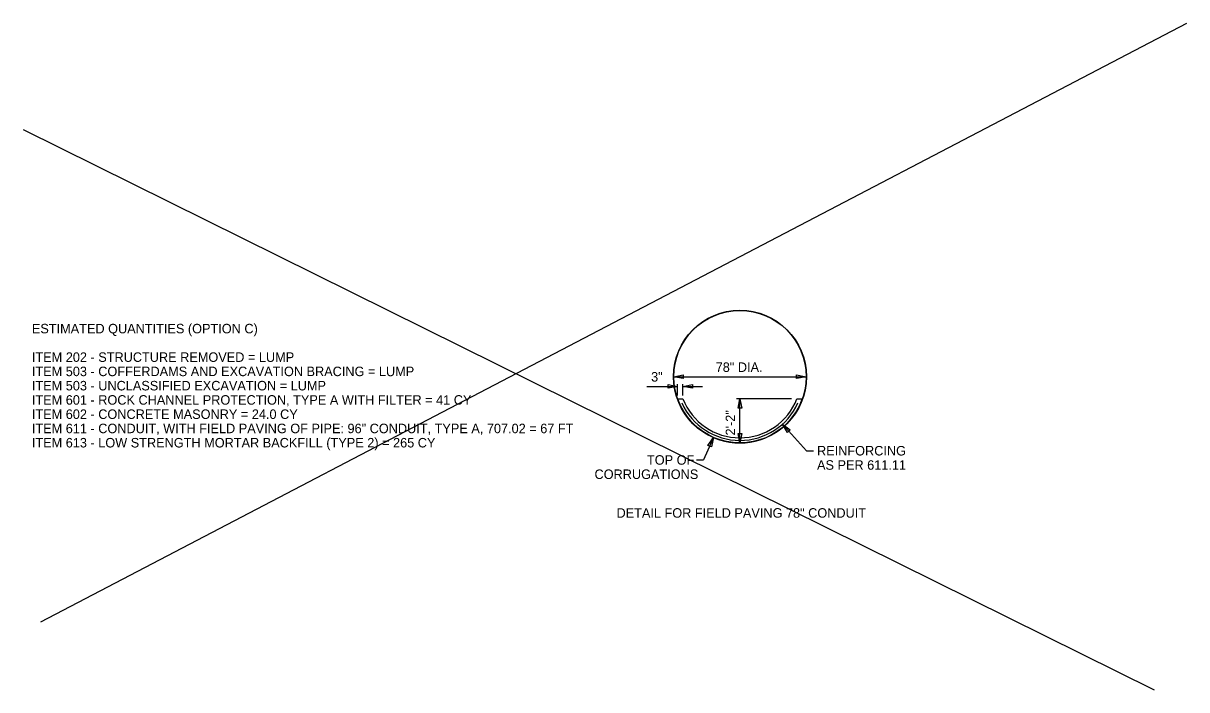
# Model space of a CAD drawing. Extents: x -42 to 540, y 0 to 220.
# Drawn here: x 369 to 540.4, y 79.8 to 177.9 of the extents above; entities that cross this region are included whole.
import ezdxf

# ---------------------------------------------------------------- set-up
doc = ezdxf.new("R2010")
doc.units = 0
for name, color, linetype in [('DR_P_Headwall', 7, 'Continuous'), ('DR_X_Culvert', 7, 'Continuous'), ('SH_Border', 7, 'Continuous'), ('SH_Data', 7, 'Continuous'), ('XS_P_Pavt_Surface', 7, 'Continuous')]:
    doc.layers.add(name, color=color, linetype=linetype)

msp = doc.modelspace()

# ---------------------------------------------------------------- linework, layer by layer
at = {"layer": 'DR_P_Headwall'}
for p, q in [((371.62, 89.77), (540.42, 177.9)), ((369.01, 162.27), (535.64, 79.78))]:
    msp.add_line(p, q, dxfattribs=at)
at = {"layer": 'DR_X_Culvert'}
for points in [[(466.24, 126.15), (466.24, 125.59), (464.84, 125.87)], [(482.94, 125.59), (482.94, 126.15), (484.34, 125.87)], [(464, 124.17), (464, 124.73), (465.4, 124.45)], [(467.6, 124.73), (467.6, 124.17), (466.2, 124.45)], [(474.87, 121.22), (474.31, 121.22), (474.59, 122.62)], [(482, 118.04), (481.58, 117.66), (480.85, 118.89)], [(470.38, 115.54), (469.87, 115.76), (470.68, 116.93)], [(474.31, 117.52), (474.87, 117.52), (474.59, 116.12)]]:
    msp.add_lwpolyline(points, close=True, dxfattribs=at)
at = {"layer": 'SH_Border'}
for radius in [9.79, 9.75]:
    msp.add_circle((474.59, 125.87), radius, dxfattribs=at)
at = {"layer": 'SH_Data'}
for p, q in [((464.84, 125.87), (484.34, 125.87)), ((460.89, 124.45), (465.4, 124.45)), ((465.4, 123.08), (465.4, 124.78)), ((466.2, 123.08), (466.2, 124.78)), ((466.2, 124.45), (469.08, 124.45)), ((465.4, 122.62), (466.2, 122.62)), ((465.4, 122.62), (466.2, 122.62)), ((482.2, 122.62), (474.09, 122.62)), ((474.59, 116.12), (474.59, 122.62)), ((482.98, 122.62), (483.78, 122.62)), ((482.98, 122.62), (483.78, 122.62)), ((480.85, 118.89), (484.38, 114.97)), ((470.68, 116.93), (469.23, 113.61)), ((484.38, 114.97), (485.42, 114.97)), ((468.18, 113.61), (469.23, 113.61))]:
    msp.add_line(p, q, dxfattribs=at)
for radius, start, end in [(9.75, 199.4712, 340.5288), (9, 201.1684, 338.8316), (9, 201.1684, 338.8316)]:
    msp.add_arc((474.59, 125.87), radius, start, end, dxfattribs=at)
at = {"layer": 'XS_P_Pavt_Surface'}
msp.add_arc((474.59, 125.87), 9.38, 204.2242, 335.7758, dxfattribs=at)

# ---------------------------------------------------------------- texts
at = {"layer": 'SH_Data'}
for s, p in [('ESTIMATED QUANTITIES (OPTION C)', (370.28, 132.25)), ('ITEM 202 - STRUCTURE REMOVED = LUMP', (370.28, 128.05)), ('ITEM 503 - COFFERDAMS AND EXCAVATION BRACING = LUMP', (370.28, 125.95)), ('78" DIA.', (471.02, 126.57)), ('ITEM 503 - UNCLASSIFIED EXCAVATION = LUMP', (370.28, 123.85)), ('3"', (461.51, 125.15)), ('ITEM 601 - ROCK CHANNEL PROTECTION, TYPE A WITH FILTER = 41 CY', (370.28, 121.75)), ('ITEM 602 - CONCRETE MASONRY = 24.0 CY', (370.28, 119.65)), ('ITEM 611 - CONDUIT, WITH FIELD PAVING OF PIPE: 96" CONDUIT, TYPE A, 707.02 = 67 FT', (370.28, 117.55)), ('ITEM 613 - LOW STRENGTH MORTAR BACKFILL (TYPE 2) = 265 CY', (370.28, 115.45)), ('REINFORCING', (485.95, 114.27)), ('TOP OF', (460.9, 112.91)), ('AS PER 611.11', (485.95, 112.17)), ('CORRUGATIONS', (453.17, 110.81)), ('DETAIL FOR FIELD PAVING 78" CONDUIT', (456.41, 105.11))]:
    msp.add_text(s, height=1.4, dxfattribs=at).set_placement(p)
msp.add_text('2\'-2"', height=1.4, rotation=90, dxfattribs=at).set_placement((473.89, 117.21))

doc.saveas('drawing.dxf')
